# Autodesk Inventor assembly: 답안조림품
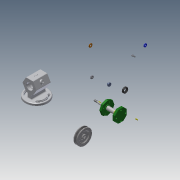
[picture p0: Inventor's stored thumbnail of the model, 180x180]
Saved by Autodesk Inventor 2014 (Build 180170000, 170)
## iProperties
Created: 2017-06
Part Number: 답안조림품
Document SubType Name: Assembly
Designer: user
Author: user
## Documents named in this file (14)
- C:\Users\user\Desktop\470608V1002\답안조림품.iam
- C:\Users\user\Desktop\470608V1002\470608V1002.ipt
- C:\Users\user\Desktop\470608V1002\V벨트풀리.ipt
- C:\Users\user\Desktop\470608V1002\고무캡.ipt
- C:\Users\user\Desktop\470608V1002\너트 M 8.ipt
- C:\Users\user\Desktop\470608V1002\뒤커버.ipt
- C:\Users\user\Desktop\470608V1002\베어링 15 x 32 x 9.ipt
- C:\Users\user\Desktop\470608V1002\볼트 M4 x 12.ipt
- C:\Users\user\Desktop\470608V1002\스프링와셔 8.ipt
- C:\Users\user\Desktop\470608V1002\앞커버.ipt
- C:\Users\user\Desktop\470608V1002\오일 실 15 25 7.ipt
- C:\Users\user\Desktop\470608V1002\와셔 8x17.ipt
- C:\Users\user\Desktop\470608V1002\축.ipt
- C:\Users\user\Desktop\470608V1002\키 3 x 3 x 12.ipt
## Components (3 placed, 3 different names)
1. 470608V1002:1
2. V벨트풀리:1
3. 고무캡:1
